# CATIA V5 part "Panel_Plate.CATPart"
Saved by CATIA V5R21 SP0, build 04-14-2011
Part number: LCD
Bounding box of the stored display mesh (mm): x -92.6 to 92.6, y -50 to 50, z 0 to 2.8
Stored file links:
  C:\Users\Pouria\Desktop\Box\Panel_Plate.CATPart
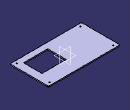
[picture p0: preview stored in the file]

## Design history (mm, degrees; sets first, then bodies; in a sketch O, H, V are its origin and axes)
Body1 (main body)
  Sketch1 on xy-plane, origin (0, 0, 0), H (1, 0, 0), V (0, 1, 0)
    line L1 (92.8, 50) -> (92.8, 20)
    line L2 (92.8, -50) -> (-92.8, -50)
    line L3 (-92.8, -50) -> (-92.8, -20)
    line L4 (-92.8, 50) -> (92.8, 50)
    point P1 (92.8, 50)
    point P2 (92.8, -50)
    line L5 (9.8, 13) -> (72.8, 13)
    line L6 (72.8, 13) -> (72.8, -35)
    line L7 (72.8, -35) -> (9.8, -35)
    line L8 (9.8, -35) -> (9.8, 13)
    line L9 (92.8, 20) -> (90, 20)
    line L10 (90, 20) -> (90, -20)
    line L11 (90, -20) -> (92.8, -20)
    point P12 (92.8, -20)
    point P13 (-92.8, 20)
    line L12 (-92.8, 20) -> (-90, 20)
    line L13 (-90, 20) -> (-90, -20)
    line L14 (-90, -20) -> (-92.8, -20)
    line L15 (92.8, -20) -> (92.8, -50)
    line L16 (-92.8, 20) -> (-92.8, 50)
    circle A1 centre (82.5, -42.5) radius 1.5
    point P17 (82.5, -42.5)
    circle A2 centre (82.5, 42.5) radius 1.5
    point P18 (82.5, 42.5)
    circle A3 centre (-82.5, 42.5) radius 1.5
    point P19 (-82.5, 42.5)
    circle A4 centre (-82.5, -42.5) radius 1.5
    point P20 (-82.5, -42.5)
    length L4 = 185.6
    length L5 = 63
    length L6 = 48
    distance L2 L7 = 15
    length L9 = 2.8
    length L13 = 40
    distance P1 P2 = 100
    distance L1 L6 = 20
    distance P17 L2 = 7.5
    distance P17 L10 = 7.5
    distance P20 L13 = 7.5
    distance P20 L2 = 7.5
    distance P19 L4 = 7.5
    distance P19 L13 = 7.5
    distance P18 L4 = 7.5
    distance P18 L10 = 7.5
    radius A2 = 1.5
    radius A3 = 1.5
    radius A4 = 1.5
    radius A1 = 1.5
    vertical: L1 V, L3 V, L6 V, L8 V, L10 V, L13 V, L15 V, L16 V
    horizontal: L2 H, L4 H, L5 H, L7 H, L9 H, L11 H, L12 H, L14 H
    equidistance: L1 L3 O, L2 L4 O
    coincidence: P12 L1, P13 L3, L9 L12, L11 L14, L1 L15, L3 L16
    symmetry: L12 L14 H, L11 L9 H, L10 L13 V
  Pad1: profile Sketch1, direction (0, 0, 1), length 2.8
  Sketch2 on end face of Pad1, origin (0, 0, 2.8), H (1, 0, 0), V (0, 1, 0)
    circle A1 centre (76.55, -33.1) radius 1.6
    point P1 (76.55, -33.1)
    circle A2 centre (0.65, -33.1) radius 1.6
    point P2 (0.65, -33.1)
    circle A3 centre (0.65, 11.1) radius 1.6
    point P3 (0.65, 11.1)
    circle A4 centre (76.55, 11.1) radius 1.6
    point P4 (76.55, 11.1)
    radius A4 = 1.6
    radius A1 = 1.6
    radius A3 = 1.6
    radius A2 = 1.6
    distance P3 V = 0.65
    distance P3 H = 11.1
    distance P2 V = 0.65
    distance P2 H = 33.1
    distance P1 V = 76.55
    distance P1 H = 33.1
    distance P4 V = 76.55
    distance P4 H = 11.1
  Pocket1: profile Sketch2, direction (0, 0, -1), through (limit type 6)
  Sketch3 on end face of Pad1, origin (0, 0, 2.8), H (1, 0, 0), V (0, 1, 0)
    line L1 (72.8, 25.4528) -> (92.8, 25.4528)
    line L2 (92.8, 25.4528) -> (92.8, -36.367)
    line L3 (92.8, -36.367) -> (72.8, -36.367)
    line L4 (72.8, -36.367) -> (72.8, 25.4528)
    line L5 (9.8, -37.5525) -> (-92.8, -37.5525)
    line L6 (-92.8, -37.5525) -> (-92.8, 31.2114)
    line L7 (-92.8, 31.2114) -> (9.8, 31.2114)
    line L8 (9.8, 31.2114) -> (9.8, -37.5525)
    reference projected line E1 (92.8, 20) -> (92.8, 50) from edge [face of Pad1 from Sketch1.L1 | end face of Pad1]
    reference projected line E2 (72.8, -35) -> (72.8, 13) from edge [end face of Pad1 | face of Pad1 from Sketch1.L6]
    reference projected line E3 (9.8, 13) -> (9.8, -35) from edge [end face of Pad1 | face of Pad1 from Sketch1.L8]
    reference projected line E4 (-92.8, -20) -> (-92.8, -50) from edge [face of Pad1 from Sketch1.L3 | end face of Pad1]
    horizontal: L1 H, L3 H, L5 H, L7 H
    vertical: L2 V, L4 V, L6 V, L8 V
    coincidence: L2 E1, L4 E2, L8 E3, L6 E4
  Pad2: profile Sketch3, direction (0, 0, 1), up to start face of Pad1
  Sketch4 on face of Pad1, origin (0, 0, 2.8), H (1, 0, 0), V (0, 1, 0)
    line L1 (110.9869, 58.4596) -> (92.6, 58.4596)
    line L2 (92.6, 58.4596) -> (92.6, -63.793)
    line L3 (92.6, -63.793) -> (110.9869, -63.793)
    line L4 (110.9869, -63.793) -> (110.9869, 58.4596)
    line L5 (-110.9869, 61.7426) -> (-92.6, 61.7426)
    line L6 (-92.6, 61.7426) -> (-92.6, -53.006)
    line L7 (-92.6, -53.006) -> (-110.9869, -53.006)
    line L8 (-110.9869, -53.006) -> (-110.9869, 61.7426)
    reference projected line E1 (-92.8, -50) -> (-92.8, -20) from edge [face of Pad1 | face of Pad1]
    reference projected line E3 (92.8, -20) -> (92.8, -50) from edge [face of Pad1 | face of Pad1]
    distance L6 E1 = 0.2
    distance L2 E3 = 0.2
    horizontal: L1 H, L3 H, L5 H, L7 H
    vertical: L2 V, L4 V, L6 V, L8 V
  Pocket2: profile Sketch4, direction (0, 0, -1), through (limit type 3)
  Fillet1: radius 2, on edge [face of Pocket2 from Sketch4.L2 | face of Pad1 from Sketch1.L4]; edge [face of Pad1 from Sketch1.L2 | face of Pocket2 from Sketch4.L2]; edge [face of Pocket2 from Sketch4.L6 | face of Pad1 from Sketch1.L2]; edge [face of Pad1 from Sketch1.L4 | face of Pocket2 from Sketch4.L6]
